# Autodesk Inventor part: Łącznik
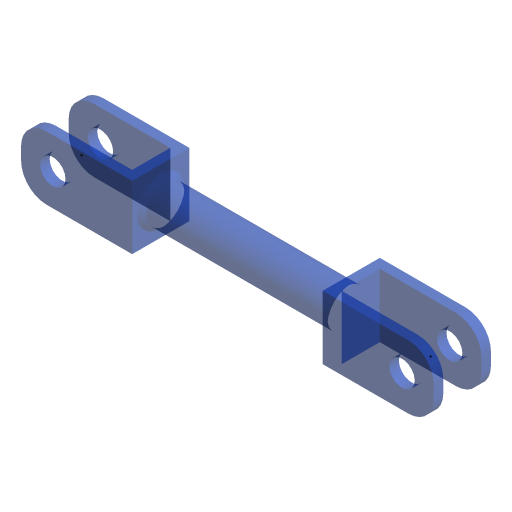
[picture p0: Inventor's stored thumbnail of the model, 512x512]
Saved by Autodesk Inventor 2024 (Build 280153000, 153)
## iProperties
Company: ATC
Shininess: 20.0
Angle Display Precision: 2
Document Length Units: 11269
Document Angle Units: 11279
Document Time Units: 11290
Document Mass Units: 11283
Document Length Units Precision: 3
Document Angle Units Precision: 2
Created: 2023-03
Part Number: Łącznik
Material: Stal węglowa
Document SubType Name: Modelowanie
Designer: Andrzej Jaskulski
Density: 7.87 g/cm^3
Stock Number: Łącznik
Mass: 124.227 g
Surface Area: 93.5667 cm^2
Volume: 15.7849 cm^3
Appearance: Przezroczyste — niebieskie
Checked By: A.J.
Engr Approved By: Andrzej Jaskulski
Mfg Approved By: Andrzej Jaskulski
Authority: A.J.
Density: 0.0
Volumn: 0.0
Area: 0.0
PropertySet Name: Model Information
Control State: 0
Master: False
Checked Out: False
Title: A.J.: Kurs R2024-MEP
Author: Andrzej Jaskulski
Revision Number: 1/24
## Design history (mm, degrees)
node "Początek"
  node "Płaszczyzna YZ"
  node "Płaszczyzna XZ"
  node "Płaszczyzna XY"
  node "Oś X"
  node "Oś Y"
  node "Oś Z"
node "Płaszczyzna konstrukcyjna1"
sketch "Szkic2"
  geometry: L1 (61.629, 12)-(29.629, 12); L2 (29.629, 0)-(61.629, 0); L3 (61.629, -3)-(26.629, -3); L4 (61.629, 12)-(61.629, 15); L5 (61.629, 15)-(26.629, 15); L6 (26.629, 15)-(26.629, -3); L7 (29.629, 12)-(29.629, 0); L8 (61.629, -3)-(61.629, 0)
  constraints: 16 end point, 4 parallel, 2 perpendicular
  dimensions: "d19" = 12 distance of L1.end L2.start; "d20" = 32 distance of L2.start L2.end; "d22" = 3 distance of L1.start L4.end; "d23" = 3 distance of L3.start L2.end (= d22); "d24" = 3 distance between parallel lines of L6 L7
extrude "Wyciągnięcie proste1" new body sketch "Szkic2" distance "d0" = 20; taper "d1" = 0 deg
sketch "Szkic3"
  geometry: L1 (0, 18)-(0, 0) reference; L2 (0, 18)-(-20, 18) reference; L3 (-20, 18)-(-20, 0) reference; C1 r 6 at (-10, 9)
  constraints: 1 centre point
  dimensions: "d4" = 12 diameter of C1; "d27" = 10 distance from line of C1.centre L3; "d28" = 9 distance from line of L2 C1.centre
extrude "Wyciągnięcie proste2" join sketch "Szkic3" distance "d5" = 60; taper "d6" = 0 deg
sketch "Szkic4"
  geometry: L1 (0, -20)-(35, -20) reference; L2 (35, 0)-(35, -20) reference; 1 further point
  dimensions: "d9" = 10 distance from line of L1 point (25, -10); "d10" = 10 distance from line of point (25, -10) L2
hole "Otwór1" sketch "Szkic4" diameter "d11" = 8; stored, may be unused: countersink angle "d15" = 82 deg, drill point angle "d17" = 118 deg; dims "d12" = 6, "d13" = 4, "d14" = 2, "d16" = 8
fillet "Zaokrąglenie1" dims "d18" = 8
chamfer "Faza1" distance "d25" = 1.5; stored, may be unused: second distance "d26" = 1.5, angle "d30" = 45 deg
node "Oś konstrukcyjna"
node "Oś konstrukcyjna3"
node "Płaszczyzna konstrukcyjna2"
mirror "Lustro1"
node "Oś konstrukcyjna4"
node "Przecięcie osi1"
node "Przecięcie osi2"
node "Bryła1"
node "Korpusy bryłowe"
node "Korpusy powierzchniowe"
node "Punkt środkowy"
other parameters: "sa_eq_min" = 2672.96, "sa_eq_max" = 154483, "sa_pmax_min" = -3917.54, "sa_pmax_max" = 186600, "sa_pmin_min" = -96857.1, "sa_pmin_max" = 24527.7, "sa_d_min" = 0.00004, "sa_d_max" = 0.00058, "d71" = 0, "d72" = 0, "d73" = 0, "d74" = 460.5, "d75" = 0, "d76" = -81274.8, "d77" = 0, "d78" = 0, "d79" = 0, "d80" = -546, "d81" = 0, "d82" = 5288, "d83" = 51452, "d84" = 0, "d85" = 292, "d86" = -49736, "d87" = 0, "d88" = -5135, "d90" = 18.4607
